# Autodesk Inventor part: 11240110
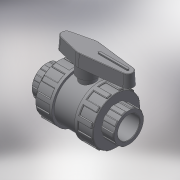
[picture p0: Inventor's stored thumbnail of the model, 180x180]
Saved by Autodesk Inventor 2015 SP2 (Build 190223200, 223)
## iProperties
Created: 2017-11
Part Number: 11240110
Material: Generic
Description: PLASSON BI STOP VALVE CEM PVC 110
Document SubType Name: Modeling
Designer: KIM
Density: 1 g/cm^3
Appearance: Default
Author: KIM
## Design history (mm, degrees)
derived "112400 - 112700.ipt"
feature "Solid1::112400 - 112700.ipt"
tag "TaggingFeature1"
body "Solid1"
other parameters: "d0" = 295, "d2" = 207, "d3" = 61, "d4" = 88, "d5" = 42.7, "d7" = 154, "d8" = 186.3, "d13" = 3.3, "d23" = 61, "d24" = 198.72, "d25" = 2.2, "d26" = 3.3, "d27" = 31.05, "d28" = 15.525, "d29" = 45.75, "d30" = 0, "d35" = 3.3, "d39" = 103.5, "d45" = 360 deg, "d47" = 2.2, "d50" = 113.85, "d51" = 62.1, "d53" = 0, "d55" = 22, "d56" = 11, "d57" = 42.7, "d58" = 0, "d59" = 3.3, "d61" = 360 deg, "d63" = 82.8, "d64" = 173, "d66" = 185, "d68" = 41.4, "d69" = 55.5, "d70" = 43.25, "d71" = 3 deg, "d73" = 4.14, "d74" = 74, "d75" = 5.19, "d76" = 0, "d77" = 2.2, "l_" = 61, "H_" = 295, "K_" = 207, "F_" = 173, "J_" = 185, "d67" = 82.8, "d72" = 20.7
